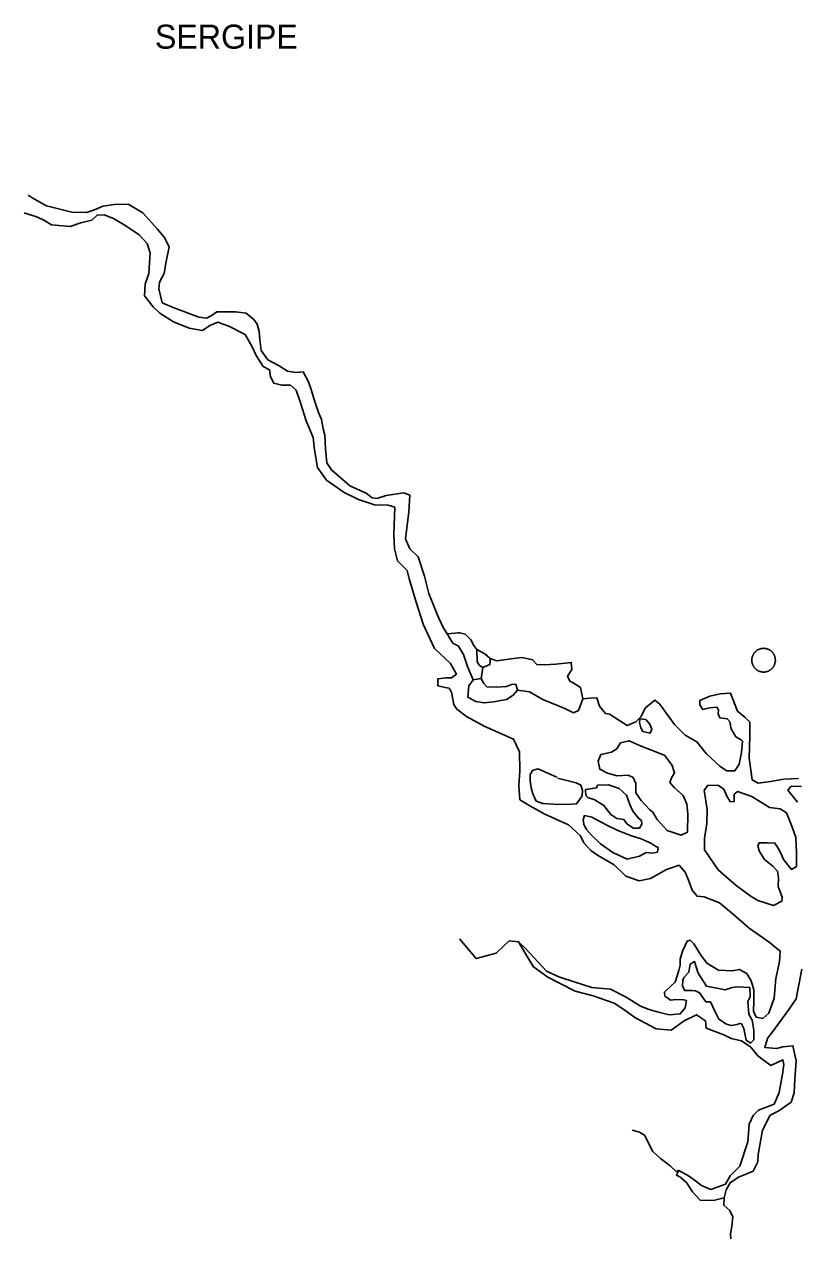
# Model space of a CAD drawing. Extents: x 662444 to 1640468, y 7452018 to 9606170.
# Drawn here: x 1332583 to 1354329, y 8754779 to 8788982 of the extents above; entities that cross this region are included whole.
import ezdxf

# ---------------------------------------------------------------- set-up
doc = ezdxf.new("R2010")
doc.units = 0
doc.layers.add('Level 1', color=7, linetype='Continuous')
doc.layers.add('Level 3', color=7, linetype='Continuous')

msp = doc.modelspace()

# ---------------------------------------------------------------- linework, layer by layer
at = {"layer": 'Level 1'}
for points in [[(1332695, 8784168), (1332803, 8784098), (1333205, 8783865), (1333917, 8783691), (1334336, 8783680), (1334559, 8783753), (1334793, 8783858), (1335180, 8783916), (1335522, 8783907), (1335924, 8783674), (1336320, 8783217), (1336524, 8782989), (1336660, 8782718), (1336571, 8782251), (1336520, 8781963), (1336392, 8781720), (1336366, 8781531), (1336466, 8781138), (1336771, 8781008), (1337492, 8780733), (1337712, 8780705), (1337846, 8780769), (1338003, 8780887), (1338532, 8780885), (1338829, 8780844), (1339045, 8780671), (1339141, 8780535), (1339191, 8780333), (1339218, 8780098), (1339254, 8779796), (1339435, 8779534), (1339761, 8779359), (1339989, 8779208), (1340231, 8779179), (1340430, 8779196), (1340588, 8778913), (1340660, 8778700), (1340730, 8778441), (1340864, 8778047), (1340947, 8777855), (1340995, 8777586), (1341046, 8777407), (1341058, 8777027), (1341103, 8776635), (1341230, 8776431), (1341748, 8775983), (1342206, 8775781), (1342378, 8775643), (1342510, 8775628), (1342766, 8775711), (1343264, 8775787), (1343439, 8775716), (1343405, 8775248), (1343319, 8774492), (1343433, 8774210), (1343670, 8773981), (1343854, 8773440), (1343974, 8772946), (1344212, 8772337), (1344369, 8772010), (1344643, 8771556), (1344806, 8771463), (1344944, 8771236), (1345056, 8770898), (1345223, 8770515), (1345097, 8770351), (1345067, 8770028), (1345295, 8769910), (1345526, 8769871), (1345791, 8769897), (1346157, 8769966), (1346347, 8770084), (1346472, 8770226), (1346802, 8770184), (1347182, 8769962), (1347804, 8769711), (1348043, 8769593), (1348188, 8769657), (1348307, 8769988), (1348517, 8770005), (1348705, 8770011), (1348776, 8769775), (1348947, 8769570), (1349057, 8769556), (1349317, 8769382), (1349555, 8769230), (1349801, 8769336), (1349937, 8769477), (1350075, 8769730), (1350335, 8769947), (1350475, 8769831), (1350667, 8769570), (1350890, 8769262), (1351191, 8768964), (1351517, 8768777), (1351784, 8768447), (1352171, 8768079), (1352366, 8767952), (1352587, 8767957), (1352713, 8768143), (1352777, 8768477)], [(1340516, 8777811), (1340363, 8778317), (1340240, 8778677), (1340078, 8778815), (1339836, 8778821), (1339606, 8778872), (1339511, 8779053), (1339483, 8779254), (1339309, 8779348), (1339107, 8779654), (1338993, 8779914), (1338803, 8780242), (1338356, 8780466), (1338029, 8780597), (1337806, 8780502), (1337604, 8780362), (1337220, 8780428), (1336783, 8780606), (1336403, 8780850), (1336209, 8781022), (1335964, 8781330), (1335983, 8781664), (1336090, 8781962), (1336127, 8782542), (1336045, 8782811), (1335820, 8783051), (1335440, 8783306), (1335093, 8783516), (1334831, 8783612), (1334632, 8783606), (1334485, 8783465), (1334175, 8783394), (1333874, 8783290), (1333346, 8783337), (1333129, 8783465), (1332955, 8783548), (1332583, 8783669)], [(1348558, 8761857), (1349086, 8761810), (1349532, 8761586), (1349933, 8761330), (1350173, 8761235), (1350435, 8761161), (1350742, 8761086), (1350853, 8761094), (1351051, 8761111), (1351188, 8761286), (1351227, 8761486), (1351150, 8761510), (1350930, 8761516), (1350775, 8761498), (1350613, 8761614), (1350605, 8761726), (1350808, 8761910), (1350910, 8762008), (1351006, 8762329), (1351043, 8762484), (1351048, 8762651), (1351109, 8762873), (1351249, 8763160), (1351327, 8763191), (1351434, 8763088), (1351635, 8762759), (1351795, 8762543), (1352131, 8762344), (1352516, 8762323), (1352716, 8762362), (1352922, 8762245), (1353049, 8762041), (1353120, 8761793), (1353122, 8761458), (1353115, 8761191), (1353188, 8761021), (1353374, 8760983), (1353543, 8761135), (1353698, 8761555), (1353745, 8762112), (1353846, 8762578), (1353865, 8762879), (1353552, 8763132), (1352989, 8763527), (1352547, 8763907), (1352159, 8764241), (1351722, 8764408), (1351524, 8764425), (1351385, 8764596), (1351283, 8764877), (1351189, 8765103), (1351018, 8765297), (1350662, 8765173), (1350215, 8764928), (1349893, 8764858), (1349522, 8764990), (1349188, 8765312), (1348721, 8765580), (1348537, 8765708), (1348334, 8765925), (1348240, 8766129), (1347906, 8766439), (1347241, 8766735), (1346817, 8766969), (1346535, 8767144), (1346502, 8767547), (1346535, 8767959), (1346526, 8768495), (1346359, 8768845), (1345531, 8769212), (1345031, 8769482), (1344760, 8769690), (1344676, 8769826), (1344608, 8770174), (1344544, 8770287), (1344435, 8770301), (1344226, 8770351), (1344221, 8770552), (1344464, 8770579), (1344607, 8770575), (1344753, 8770683), (1344584, 8770978), (1344132, 8771402), (1343808, 8772091), (1343625, 8772676), (1343422, 8773362), (1343362, 8773598), (1343094, 8773873), (1343003, 8774210), (1342991, 8774612), (1343005, 8775125), (1343011, 8775381), (1342825, 8775442), (1342440, 8775452), (1341991, 8775597), (1341589, 8775797), (1341090, 8776145), (1340835, 8776497), (1340749, 8777001), (1340713, 8777348), (1340516, 8777811)], [(1345322, 8771371), (1345237, 8771485), (1345153, 8771644), (1344992, 8771804), (1344849, 8771841), (1344794, 8771843), (1344507, 8771816)], [(1348307, 8769988), (1348238, 8770302), (1348032, 8770431), (1347945, 8770477), (1347872, 8770624), (1347998, 8770811), (1347981, 8771012), (1347549, 8770956), (1347229, 8770942), (1347009, 8770948), (1346891, 8771085), (1346595, 8771149), (1346352, 8771121), (1345887, 8771055), (1345701, 8771116), (1345699, 8771016), (1345686, 8770949), (1345496, 8770865), (1345399, 8770923), (1345335, 8771025), (1345322, 8771371), (1345551, 8771254), (1345701, 8771116)], [(1353727, 8771063), (1353727, 8771074), (1353726, 8771087), (1353726, 8771098), (1353725, 8771110), (1353723, 8771121), (1353721, 8771133), (1353719, 8771145), (1353716, 8771156), (1353713, 8771167), (1353710, 8771179), (1353706, 8771189), (1353702, 8771200), (1353698, 8771211), (1353692, 8771222), (1353687, 8771232), (1353681, 8771242), (1353676, 8771252), (1353669, 8771261), (1353662, 8771272), (1353655, 8771281), (1353648, 8771290), (1353640, 8771298), (1353632, 8771307), (1353624, 8771315), (1353616, 8771323), (1353607, 8771330), (1353597, 8771338), (1353589, 8771345), (1353579, 8771351), (1353569, 8771358), (1353559, 8771363), (1353550, 8771369), (1353539, 8771374), (1353528, 8771379), (1353518, 8771384), (1353507, 8771387), (1353496, 8771391), (1353485, 8771394), (1353473, 8771397), (1353462, 8771399), (1353451, 8771402), (1353439, 8771403), (1353428, 8771405), (1353416, 8771406), (1353405, 8771407), (1353394, 8771407), (1353382, 8771406), (1353371, 8771405), (1353359, 8771404), (1353348, 8771402), (1353336, 8771401), (1353324, 8771399), (1353313, 8771396), (1353302, 8771393), (1353291, 8771389), (1353281, 8771385), (1353270, 8771381), (1353259, 8771377), (1353249, 8771372), (1353239, 8771366), (1353228, 8771360), (1353218, 8771355), (1353209, 8771348), (1353199, 8771341), (1353190, 8771334), (1353181, 8771326), (1353173, 8771319), (1353164, 8771310), (1353156, 8771303), (1353148, 8771294), (1353142, 8771285), (1353134, 8771275), (1353127, 8771267), (1353121, 8771257), (1353114, 8771247), (1353108, 8771237), (1353103, 8771227), (1353098, 8771216), (1353093, 8771205), (1353089, 8771195), (1353085, 8771184), (1353081, 8771173), (1353078, 8771162), (1353075, 8771150), (1353073, 8771138), (1353070, 8771127), (1353069, 8771115), (1353067, 8771104), (1353066, 8771092), (1353066, 8771081), (1353065, 8771069), (1353066, 8771057), (1353067, 8771046), (1353068, 8771034), (1353070, 8771022), (1353072, 8771011), (1353073, 8770999), (1353076, 8770988), (1353079, 8770976), (1353082, 8770965)], [(1353082, 8770965), (1353087, 8770955), (1353091, 8770944), (1353095, 8770933), (1353100, 8770922), (1353105, 8770912), (1353112, 8770902), (1353117, 8770892), (1353123, 8770883), (1353131, 8770872), (1353137, 8770863), (1353145, 8770854), (1353152, 8770846), (1353161, 8770837), (1353168, 8770829), (1353177, 8770821), (1353185, 8770814), (1353195, 8770806), (1353204, 8770799), (1353214, 8770793), (1353223, 8770786), (1353233, 8770780), (1353243, 8770775), (1353254, 8770770), (1353265, 8770765), (1353275, 8770760), (1353285, 8770757), (1353296, 8770753), (1353307, 8770750), (1353319, 8770747), (1353330, 8770744), (1353341, 8770742), (1353353, 8770740), (1353364, 8770739), (1353376, 8770738), (1353387, 8770737), (1353399, 8770737), (1353411, 8770738), (1353422, 8770739), (1353434, 8770739), (1353445, 8770741), (1353456, 8770743), (1353468, 8770745), (1353479, 8770748), (1353490, 8770751), (1353502, 8770754), (1353512, 8770759), (1353523, 8770763), (1353534, 8770767), (1353544, 8770772), (1353554, 8770778), (1353564, 8770784), (1353574, 8770789), (1353583, 8770796), (1353593, 8770803), (1353602, 8770810), (1353611, 8770817), (1353619, 8770825), (1353628, 8770834), (1353636, 8770841), (1353644, 8770850), (1353651, 8770859), (1353659, 8770869), (1353666, 8770877), (1353671, 8770887), (1353678, 8770897), (1353684, 8770907), (1353690, 8770917), (1353695, 8770928), (1353699, 8770939), (1353704, 8770949), (1353708, 8770960), (1353711, 8770971), (1353715, 8770982), (1353717, 8770994), (1353720, 8771005), (1353722, 8771017), (1353724, 8771029), (1353725, 8771040), (1353727, 8771052), (1353727, 8771063)], [(1345496, 8770865), (1345444, 8770554), (1345223, 8770515)], [(1345444, 8770554), (1345518, 8770418), (1345604, 8770326), (1345879, 8770308), (1346155, 8770334), (1346300, 8770386), (1346421, 8770394), (1346472, 8770226)], [(1352777, 8768477), (1352807, 8768788), (1352764, 8768834), (1352612, 8768916), (1352486, 8769143), (1352447, 8769333), (1352372, 8769425), (1352163, 8769452), (1352122, 8769565), (1352125, 8769677), (1352082, 8769745), (1351873, 8769728), (1351684, 8769688), (1351599, 8769813), (1351602, 8769936), (1351881, 8770062), (1352170, 8770122), (1352468, 8770148), (1352582, 8769854), (1352664, 8769640), (1352869, 8769467), (1353009, 8769330), (1353010, 8768939), (1352993, 8768315), (1353076, 8767699), (1353239, 8767605), (1353593, 8767652), (1353970, 8767720), (1354379, 8767743)], [(1349992, 8769063), (1349939, 8769165), (1349899, 8769322), (1349913, 8769422), (1350078, 8769406), (1350196, 8769269), (1350247, 8769134), (1350200, 8769013), (1349992, 8769063)], [(1350406, 8768472), (1350614, 8768388), (1350827, 8768103), (1350888, 8767901), (1350807, 8767758), (1350759, 8767625), (1350888, 8767477), (1351135, 8767258), (1351240, 8767021), (1351265, 8766742), (1351252, 8766229), (1351073, 8766144), (1350680, 8766277), (1350401, 8766586), (1350274, 8766790), (1350188, 8766870), (1349952, 8767122), (1349804, 8767338), (1349799, 8767595), (1349726, 8767764), (1349585, 8767835), (1349276, 8767820), (1349002, 8767894), (1348785, 8768001), (1348735, 8768225), (1348817, 8768413), (1349117, 8768483), (1349263, 8768580), (1349366, 8768744), (1349610, 8768805), (1349948, 8768651), (1350406, 8768472)], [(1347598, 8767752), (1347894, 8767678), (1348124, 8767616), (1348255, 8767557), (1348295, 8767411), (1348291, 8767255), (1348131, 8767024), (1347844, 8767010), (1347480, 8767019), (1347183, 8767038), (1346997, 8767099), (1346904, 8767313), (1346853, 8767482), (1346825, 8767672), (1346829, 8767851), (1346887, 8767961), (1347043, 8768012), (1347174, 8767953), (1347577, 8767775)], [(1348718, 8767556), (1349027, 8767559), (1349333, 8767462), (1349537, 8767267), (1349630, 8767008), (1349713, 8766816), (1349873, 8766622), (1349959, 8766553), (1349968, 8766452), (1349899, 8766342), (1349734, 8766346), (1349549, 8766463), (1349464, 8766588), (1349267, 8766615), (1349093, 8766731), (1348901, 8766982), (1348630, 8767145), (1348455, 8767194), (1348401, 8767252), (1348382, 8767364), (1348384, 8767431), (1348694, 8767478), (1348718, 8767556)], [(1352117, 8765168), (1351735, 8765736), (1351732, 8766049), (1351798, 8766471), (1351809, 8766861), (1351752, 8767231), (1351723, 8767399), (1351827, 8767553), (1352124, 8767545), (1352276, 8767441), (1352369, 8767226), (1352454, 8767090), (1352564, 8767087), (1352570, 8767299), (1352660, 8767375), (1353064, 8767230), (1353563, 8766927), (1353860, 8766886), (1354044, 8766769), (1354189, 8766397), (1354302, 8766082), (1354324, 8765657), (1354325, 8765266), (1354179, 8765181), (1353955, 8765455), (1353882, 8765635), (1353809, 8765782), (1353713, 8765918), (1353493, 8765924), (1353273, 8765930), (1353237, 8765831), (1353277, 8765684), (1353426, 8765457), (1353652, 8765273), (1353792, 8765135), (1353820, 8764945), (1353802, 8764700), (1353916, 8764395), (1353913, 8764284), (1353678, 8764167), (1353230, 8764302), (1353045, 8764418), (1352624, 8764731), (1352117, 8765168)], [(1354461, 8767517), (1354174, 8767525), (1354083, 8767415), (1354350, 8767074)], [(1349291, 8766280), (1349673, 8766125), (1349946, 8766040), (1350219, 8765921), (1350359, 8765828), (1350425, 8765793), (1350410, 8765670), (1350255, 8765641), (1350090, 8765656), (1349900, 8765550), (1349556, 8765469), (1349153, 8765658), (1348807, 8765902), (1348549, 8766143), (1348399, 8766314), (1348336, 8766450), (1348317, 8766573), (1348354, 8766695), (1348562, 8766656), (1348986, 8766422), (1349291, 8766280)], [(1346497, 8763139), (1346233, 8763168), (1345872, 8762820), (1345305, 8762668), (1344835, 8763227)], [(1354469, 8762372), (1354315, 8761539), (1354108, 8761232), (1353834, 8760859), (1353502, 8760422), (1353430, 8760167), (1353759, 8760136), (1353937, 8760187), (1354224, 8760213), (1354312, 8759786), (1354277, 8759274), (1354255, 8758884), (1354172, 8758629), (1353823, 8758382), (1353577, 8758254), (1353368, 8757836), (1353240, 8757147), (1353234, 8756946), (1353106, 8756682), (1352694, 8756514), (1352458, 8756353), (1352343, 8756155), (1352282, 8755934), (1351982, 8755852), (1351607, 8755862), (1351393, 8756102), (1351224, 8756363), (1351041, 8756525), (1350943, 8756572), (1351013, 8756704), (1351284, 8756552), (1351479, 8756413), (1351651, 8756274), (1351913, 8756167), (1352325, 8756312), (1352452, 8756554), (1352724, 8756826), (1352952, 8757512), (1352987, 8758002), (1353103, 8758245), (1353251, 8758397), (1353696, 8758564), (1353837, 8758895), (1353928, 8759417), (1353968, 8759684), (1353938, 8759819), (1353604, 8759660), (1353236, 8759926), (1353033, 8760177), (1352773, 8760352), (1352488, 8760415), (1352281, 8760521), (1351779, 8760713), (1351763, 8760914), (1351503, 8761088), (1351157, 8760919), (1350797, 8760649), (1350368, 8760694), (1349770, 8761011), (1349489, 8761219), (1349186, 8761417), (1348596, 8761622), (1348092, 8761747), (1347320, 8762146), (1346920, 8762436), (1346740, 8762731), (1346592, 8762980), (1346497, 8763139), (1346701, 8762944), (1347280, 8762315), (1347629, 8762150), (1348088, 8762004), (1348558, 8761857)], [(1351766, 8761450), (1351596, 8761700), (1351476, 8761758), (1351377, 8761772), (1351179, 8761766), (1351116, 8761891), (1351120, 8762058), (1351155, 8762135), (1351292, 8762288), (1351331, 8762510), (1351454, 8762585), (1351556, 8762259), (1351789, 8761895), (1352315, 8761792), (1352515, 8761854), (1352681, 8761872), (1352835, 8761868), (1353011, 8761852), (1353015, 8761595), (1352957, 8761463), (1352980, 8761105), (1353075, 8760935), (1353123, 8760655), (1353126, 8760376), (1353025, 8760289), (1352906, 8760370), (1352837, 8760696), (1352775, 8760831), (1352720, 8760844), (1352653, 8760812), (1352487, 8760783), (1352355, 8760820), (1352139, 8760960), (1352023, 8761186), (1351898, 8761446), (1351766, 8761450)], [(1351013, 8756704), (1350935, 8756672), (1350762, 8756833), (1350492, 8757041), (1350277, 8757237), (1350047, 8757700), (1349906, 8757782), (1349698, 8757832)], [(1352282, 8755934), (1352276, 8755722), (1352448, 8755572), (1352532, 8755391), (1352503, 8755135), (1352464, 8754913), (1352472, 8754779)]]:
    msp.add_lwpolyline(points, dxfattribs=at)

# ---------------------------------------------------------------- texts
at = {"layer": 'Level 3'}
msp.add_text('SERGIPE', height=676.7, dxfattribs=at).set_placement((1336261, 8788295))

doc.saveas('drawing.dxf')
